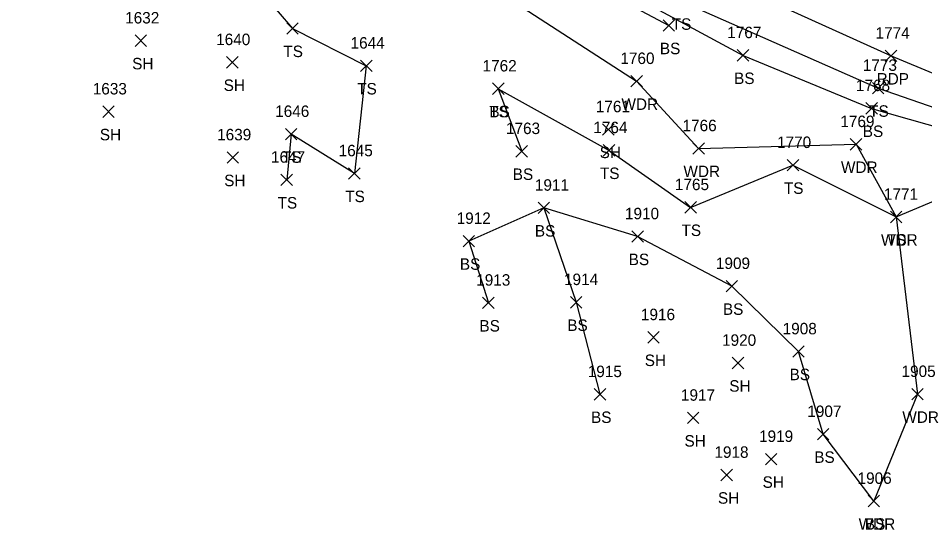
# Model space of a CAD drawing. Extents: x 1586965 to 1590952, y 716317 to 720029.
# Drawn here: x 1587975.1 to 1588133.2, y 719590 to 719679.3 of the extents above; entities that cross this region are included whole.
import ezdxf

# ---------------------------------------------------------------- set-up
doc = ezdxf.new("R2010")
doc.units = 0
for name, color, linetype in [('L_A', 7, 'Continuous'), ('L_I', 7, 'Continuous'), ('L_TIC', 7, 'Continuous'), ('LAWA', 7, 'Continuous'), ('LELB', 7, 'Continuous'), ('P_A', 7, 'Continuous'), ('P_I', 7, 'Continuous'), ('P_TIC', 7, 'Continuous'), ('PET', 7, 'Continuous')]:
    doc.layers.add(name, color=color, linetype=linetype)

msp = doc.modelspace()

# ---------------------------------------------------------------- linework, layer by layer
at = {"layer": 'L_TIC'}
for points in [[(1588021.97, 719676.49), (1588023.97, 719678.49)], [(1588023.97, 719676.49), (1588021.97, 719678.49)], [(1588087.6, 719676.99), (1588089.6, 719678.99)], [(1588089.6, 719676.99), (1588087.6, 719678.99)], [(1587995.53, 719674.35), (1587997.53, 719676.35)], [(1587997.53, 719674.35), (1587995.53, 719676.35)], [(1588100.54, 719671.79), (1588102.54, 719673.79)], [(1588102.54, 719671.79), (1588100.54, 719673.79)], [(1588011.48, 719670.58), (1588013.48, 719672.58)], [(1588013.48, 719670.58), (1588011.48, 719672.58)], [(1588034.84, 719669.97), (1588036.84, 719671.97)], [(1588036.84, 719669.97), (1588034.84, 719671.97)], [(1588081.98, 719667.28), (1588083.98, 719669.28)], [(1588083.98, 719667.28), (1588081.98, 719669.28)], [(1588057.86, 719665.98), (1588059.86, 719667.98)], [(1588059.86, 719665.98), (1588057.86, 719667.98)], [(1588057.86, 719665.98), (1588059.86, 719667.98)], [(1588059.86, 719665.98), (1588057.86, 719667.98)], [(1588124.12, 719666.08), (1588126.12, 719668.08)], [(1588126.12, 719666.08), (1588124.12, 719668.08)], [(1587989.88, 719661.97), (1587991.88, 719663.97)], [(1587991.88, 719661.97), (1587989.88, 719663.97)], [(1588122.97, 719662.55), (1588124.97, 719664.55)], [(1588124.97, 719662.55), (1588122.97, 719664.55)], [(1588077.05, 719658.87), (1588079.05, 719660.87)], [(1588079.05, 719658.87), (1588077.05, 719660.87)], [(1588021.75, 719658.05), (1588023.75, 719660.05)], [(1588023.75, 719658.05), (1588021.75, 719660.05)], [(1588092.79, 719655.56), (1588094.79, 719657.56)], [(1588094.79, 719655.56), (1588092.79, 719657.56)], [(1588120.25, 719656.28), (1588122.25, 719658.28)], [(1588122.25, 719656.28), (1588120.25, 719658.28)], [(1588011.58, 719653.97), (1588013.58, 719655.97)], [(1588013.58, 719653.97), (1588011.58, 719655.97)], [(1588061.94, 719655.06), (1588063.94, 719657.06)], [(1588063.94, 719655.06), (1588061.94, 719657.06)], [(1588077.17, 719655.22), (1588079.17, 719657.22)], [(1588079.17, 719655.22), (1588077.17, 719657.22)], [(1588109.25, 719652.63), (1588111.25, 719654.63)], [(1588111.25, 719652.63), (1588109.25, 719654.63)], [(1588032.76, 719651.19), (1588034.76, 719653.19)], [(1588034.76, 719651.19), (1588032.76, 719653.19)], [(1588020.96, 719650.07), (1588022.96, 719652.07)], [(1588022.96, 719650.07), (1588020.96, 719652.07)], [(1588065.8, 719645.18), (1588067.8, 719647.18)], [(1588067.8, 719645.18), (1588065.8, 719647.18)], [(1588065.8, 719645.18), (1588067.8, 719647.18)], [(1588067.8, 719645.18), (1588065.8, 719647.18)], [(1588091.4, 719645.28), (1588093.4, 719647.28)], [(1588093.4, 719645.28), (1588091.4, 719647.28)], [(1588127.24, 719643.6), (1588129.24, 719645.6)], [(1588129.24, 719643.6), (1588127.24, 719645.6)], [(1588127.24, 719643.6), (1588129.24, 719645.6)], [(1588129.24, 719643.6), (1588127.24, 719645.6)], [(1588082.16, 719640.2), (1588084.16, 719642.2)], [(1588084.16, 719640.2), (1588082.16, 719642.2)], [(1588052.72, 719639.39), (1588054.72, 719641.39)], [(1588054.72, 719639.39), (1588052.72, 719641.39)], [(1588098.59, 719631.53), (1588100.59, 719633.53)], [(1588100.59, 719631.53), (1588098.59, 719633.53)], [(1588056.13, 719628.62), (1588058.13, 719630.62)], [(1588058.13, 719628.62), (1588056.13, 719630.62)], [(1588071.45, 719628.72), (1588073.45, 719630.72)], [(1588073.45, 719628.72), (1588071.45, 719630.72)], [(1588084.91, 719622.6), (1588086.91, 719624.6)], [(1588086.91, 719622.6), (1588084.91, 719624.6)], [(1588110.22, 719620.13), (1588112.22, 719622.13)], [(1588112.22, 719620.13), (1588110.22, 719622.13)], [(1588099.66, 719618.13), (1588101.66, 719620.13)], [(1588101.66, 719618.13), (1588099.66, 719620.13)], [(1588075.59, 719612.67), (1588077.59, 719614.67)], [(1588077.59, 719612.67), (1588075.59, 719614.67)], [(1588130.95, 719612.69), (1588132.95, 719614.69)], [(1588132.95, 719612.69), (1588130.95, 719614.69)], [(1588091.84, 719608.55), (1588093.84, 719610.55)], [(1588093.84, 719608.55), (1588091.84, 719610.55)], [(1588114.52, 719605.71), (1588116.52, 719607.71)], [(1588116.52, 719605.71), (1588114.52, 719607.71)], [(1588105.46, 719601.36), (1588107.46, 719603.36)], [(1588107.46, 719601.36), (1588105.46, 719603.36)], [(1588097.68, 719598.59), (1588099.68, 719600.59)], [(1588099.68, 719598.59), (1588097.68, 719600.59)], [(1588123.34, 719594.05), (1588125.34, 719596.05)], [(1588125.34, 719594.05), (1588123.34, 719596.05)], [(1588123.34, 719594.05), (1588125.34, 719596.05)], [(1588125.34, 719594.05), (1588123.34, 719596.05)]]:
    msp.add_lwpolyline(points, dxfattribs=at)
at = {"layer": 'LAWA'}
msp.add_lwpolyline([(1587792.66, 719819.32), (1587813.67, 719812.11), (1587842.94, 719804.53), (1587864.87, 719797.45), (1587880.05, 719791.05), (1587889.14, 719781.4), (1587900.01, 719769.71), (1587919.42, 719757.56), (1587933.18, 719752.9), (1587956.11, 719747.4), (1587965.59, 719740.84), (1587976.83, 719735.56), (1587989.17, 719727.65), (1588001.34, 719721.18), (1588025.48, 719708.03), (1588041.3, 719690.98), (1588054.29, 719686.88), (1588082.98, 719668.28), (1588093.79, 719656.56), (1588121.25, 719657.28), (1588128.24, 719644.6), (1588131.95, 719613.69), (1588124.34, 719595.05)], dxfattribs=at)
at = {"layer": 'LELB'}
for points in [[(1587769.54, 719828.25), (1587817.81, 719818.92), (1587845.39, 719810.87), (1587866.59, 719802.16), (1587894.5, 719791.41), (1587924.64, 719774.45), (1587960.66, 719756.07), (1587994.24, 719738.05), (1588029.81, 719715.93), (1588049.13, 719705.79), (1588061.35, 719699.86), (1588090.7, 719682.25), (1588125.12, 719667.08), (1588163.84, 719653.66), (1588168.64, 719652.01), (1588170.5, 719647.84), (1588169.34, 719638.56), (1588158.94, 719617.68), (1588144.69, 719590.38)], [(1587769.54, 719828.25), (1587817.81, 719818.92), (1587845.39, 719810.87), (1587866.59, 719802.16), (1587894.5, 719791.41), (1587924.64, 719774.45), (1587960.66, 719756.07), (1587994.24, 719738.05), (1588029.81, 719715.93), (1588049.13, 719705.79), (1588061.35, 719699.86), (1588090.7, 719682.25), (1588125.12, 719667.08), (1588163.84, 719653.66), (1588168.64, 719652.01), (1588170.5, 719647.84), (1588169.34, 719638.56), (1588158.94, 719617.68), (1588144.69, 719590.38)], [(1587893.61, 719788.22), (1587923.32, 719772.46), (1587959.45, 719753.99), (1587990.31, 719736.86), (1587992.49, 719736.59), (1587993.47, 719735.49), (1587996.7, 719733.15), (1588001.37, 719729.89), (1588028.07, 719713.52), (1588047.21, 719701.72), (1588059.27, 719695.66), (1588101.54, 719672.79), (1588123.97, 719663.55), (1588153.31, 719655.21), (1588167.62, 719650.14)], [(1587893.61, 719788.22), (1587923.32, 719772.46), (1587959.45, 719753.99), (1587990.31, 719736.86), (1587992.49, 719736.59), (1587993.47, 719735.49), (1587996.7, 719733.15), (1588001.37, 719729.89), (1588028.07, 719713.52), (1588047.21, 719701.72), (1588059.27, 719695.66), (1588101.54, 719672.79), (1588123.97, 719663.55), (1588153.31, 719655.21), (1588167.62, 719650.14)], [(1587987.33, 719736.39), (1587991.65, 719733.83), (1587994.47, 719730.11), (1587999.02, 719725.54), (1588088.6, 719677.99)], [(1587987.33, 719736.39), (1587991.65, 719733.83), (1587994.47, 719730.11), (1587999.02, 719725.54), (1588088.6, 719677.99)], [(1588003.04, 719703.11), (1588010.49, 719692.09), (1588022.97, 719677.49), (1588035.84, 719670.97), (1588033.76, 719652.19), (1588022.75, 719659.05), (1588021.96, 719651.07)], [(1588003.04, 719703.11), (1588010.49, 719692.09), (1588022.97, 719677.49), (1588035.84, 719670.97), (1588033.76, 719652.19), (1588022.75, 719659.05), (1588021.96, 719651.07)], [(1588058.86, 719666.98), (1588078.17, 719656.22), (1588092.4, 719646.28), (1588110.25, 719653.63), (1588128.24, 719644.6), (1588145, 719651.67), (1588155.21, 719647.89), (1588164.26, 719643.88), (1588169.34, 719638.56)], [(1588058.86, 719666.98), (1588062.94, 719656.06)], [(1588058.86, 719666.98), (1588078.17, 719656.22), (1588092.4, 719646.28), (1588110.25, 719653.63), (1588128.24, 719644.6), (1588145, 719651.67), (1588155.21, 719647.89), (1588164.26, 719643.88), (1588169.34, 719638.56)], [(1588058.86, 719666.98), (1588062.94, 719656.06)], [(1588066.8, 719646.18), (1588053.72, 719640.39), (1588057.13, 719629.62)], [(1588066.8, 719646.18), (1588053.72, 719640.39), (1588057.13, 719629.62)], [(1588124.34, 719595.05), (1588115.52, 719606.71), (1588111.22, 719621.13), (1588099.59, 719632.53), (1588083.16, 719641.2), (1588066.8, 719646.18), (1588072.45, 719629.72), (1588076.59, 719613.67)], [(1588124.34, 719595.05), (1588115.52, 719606.71), (1588111.22, 719621.13), (1588099.59, 719632.53), (1588083.16, 719641.2), (1588066.8, 719646.18), (1588072.45, 719629.72), (1588076.59, 719613.67)]]:
    msp.add_lwpolyline(points, dxfattribs=at)
at = {"layer": 'P_TIC'}
for points in [[(1588126.35, 719671.7), (1588128.35, 719673.7)], [(1588128.35, 719671.7), (1588126.35, 719673.7)]]:
    msp.add_lwpolyline(points, dxfattribs=at)
at = {"layer": 'PET'}
msp.add_lwpolyline([(1587769.59, 719834.05), (1587819.16, 719826.14), (1587848.36, 719816.77), (1587868.73, 719807.9), (1587895.82, 719795.75), (1587926.99, 719779.02), (1587962.24, 719759.15), (1587995.65, 719740.56), (1588031.83, 719719.54), (1588060.89, 719703.68), (1588093.53, 719688.06), (1588127.35, 719672.7), (1588165.1, 719657.02), (1588195.68, 719645.12), (1588212.38, 719637.86), (1588219.86, 719635.29)], dxfattribs=at)

# ---------------------------------------------------------------- texts
at = {"layer": 'L_A'}
for s, p in [('TS', (1588089.11, 719677.25)), ('BS', (1588087.04, 719672.99)), ('TS', (1588021.38, 719672.49)), ('SH', (1587995.01, 719670.35)), ('SH', (1588010.97, 719666.58)), ('BS', (1588099.98, 719667.79)), ('TS', (1588034.25, 719665.97)), ('WDR', (1588080.34, 719663.28)), ('TS', (1588057.27, 719661.98)), ('BS', (1588057.31, 719661.98)), ('TS', (1588123.53, 719662.08)), ('BS', (1588122.42, 719658.55)), ('SH', (1587989.37, 719657.97)), ('TS', (1588021.15, 719654.05)), ('SH', (1588076.54, 719654.87)), ('WDR', (1588118.62, 719652.28)), ('BS', (1588061.38, 719651.06)), ('TS', (1588076.58, 719651.22)), ('WDR', (1588091.15, 719651.56)), ('SH', (1588011.06, 719649.97)), ('TS', (1588108.66, 719648.63)), ('TS', (1588020.37, 719646.07)), ('TS', (1588032.17, 719647.19)), ('BS', (1588065.24, 719641.18)), ('BS', (1588065.24, 719641.18)), ('TS', (1588090.81, 719641.28)), ('WDR', (1588125.6, 719639.6)), ('TS', (1588126.65, 719639.6)), ('BS', (1588052.16, 719635.39)), ('BS', (1588081.6, 719636.2)), ('BS', (1588098.03, 719627.53)), ('BS', (1588055.57, 719624.62)), ('BS', (1588070.89, 719624.72)), ('SH', (1588084.4, 719618.6)), ('BS', (1588109.66, 719616.13)), ('SH', (1588099.14, 719614.13)), ('BS', (1588075.03, 719608.67)), ('WDR', (1588129.32, 719608.69)), ('SH', (1588091.33, 719604.55)), ('BS', (1588113.96, 719601.71)), ('SH', (1588104.95, 719597.36)), ('SH', (1588097.17, 719594.59)), ('WDR', (1588121.7, 719590.05)), ('BS', (1588122.78, 719590.05))]:
    msp.add_text(s, height=2, dxfattribs=at).set_placement(p)
at = {"layer": 'L_I'}
for s, p in [('1632', (1587993.79, 719678.35)), ('1640', (1588009.66, 719674.58)), ('1767', (1588098.79, 719675.79)), ('1644', (1588033.1, 719673.97)), ('1760', (1588080.15, 719671.28)), ('1762', (1588056.12, 719669.98)), ('1762', (1588056.12, 719669.98)), ('1773', (1588122.43, 719670.08)), ('1768', (1588121.23, 719666.55)), ('1633', (1587988.14, 719665.97)), ('1646', (1588019.95, 719662.05)), ('1761', (1588075.87, 719662.87)), ('1769', (1588118.51, 719660.28)), ('1763', (1588060.2, 719659.06)), ('1764', (1588075.43, 719659.22)), ('1766', (1588090.99, 719659.56)), ('1639', (1588009.83, 719657.97)), ('1770', (1588107.47, 719656.63)), ('1647', (1588019.22, 719654.07)), ('1645', (1588031.02, 719655.19)), ('1911', (1588065.24, 719649.18)), ('1911', (1588065.24, 719649.18)), ('1765', (1588089.66, 719649.28)), ('1771', (1588126.11, 719647.6)), ('1771', (1588126.11, 719647.6)), ('1912', (1588051.6, 719643.39)), ('1910', (1588080.95, 719644.2)), ('1909', (1588096.81, 719635.53)), ('1913', (1588055.01, 719632.62)), ('1914', (1588070.32, 719632.72)), ('1916', (1588083.73, 719626.6)), ('1908', (1588108.45, 719624.13)), ('1920', (1588097.88, 719622.13)), ('1915', (1588074.46, 719616.67)), ('1905', (1588129.18, 719616.69)), ('1917', (1588090.71, 719612.55)), ('1907', (1588112.75, 719609.71)), ('1919', (1588104.33, 719605.36)), ('1918', (1588096.55, 719602.59)), ('1906', (1588121.51, 719598.05)), ('1906', (1588121.51, 719598.05))]:
    msp.add_text(s, height=2, dxfattribs=at).set_placement(p)
at = {"layer": 'P_A'}
msp.add_text('RDP', height=2, dxfattribs=at).set_placement((1588124.83, 719667.7))
at = {"layer": 'P_I'}
msp.add_text('1774', height=2, dxfattribs=at).set_placement((1588124.65, 719675.7))

doc.saveas('drawing.dxf')
